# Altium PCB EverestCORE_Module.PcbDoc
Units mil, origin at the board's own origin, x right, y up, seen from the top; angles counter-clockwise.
Board outline not stored, 6 copper layers (Top Layer, Mid-Layer 1, Mid-Layer 2, Mid-Layer 3, Mid-Layer 4, Bottom Layer); 17 components, 0 nets, 306 pads, 67 vias.
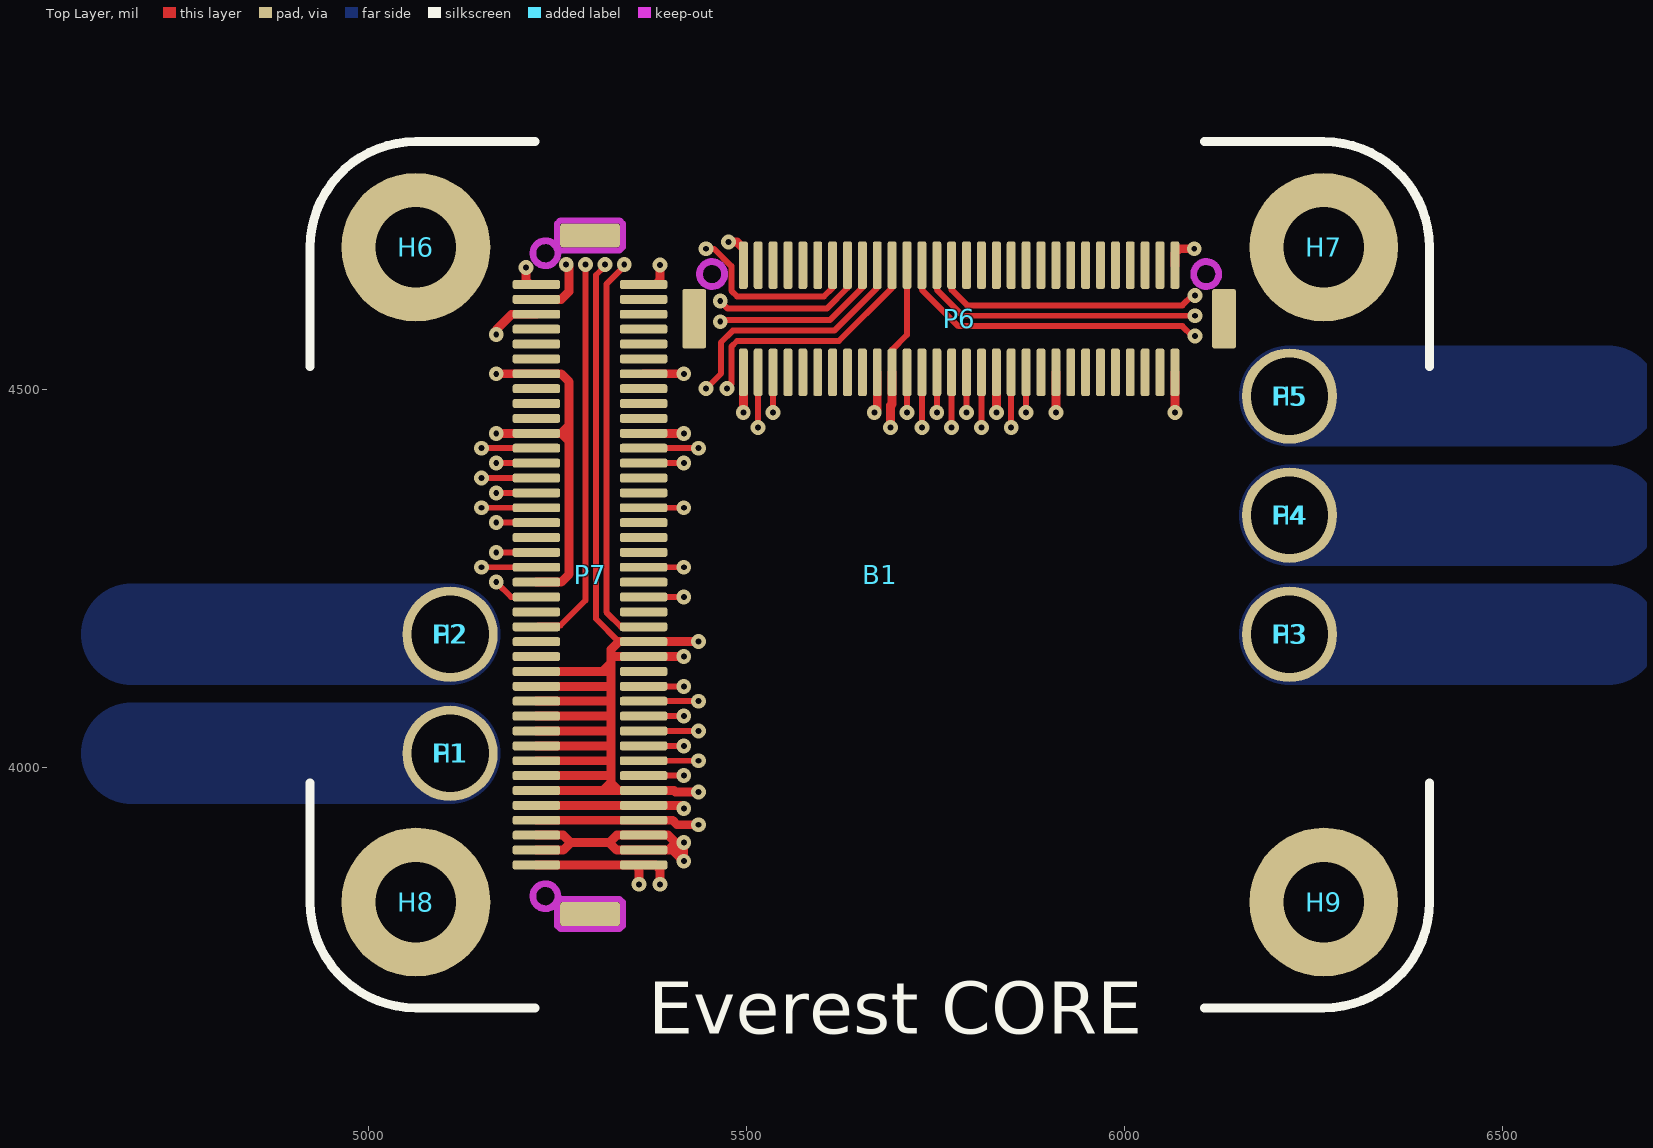
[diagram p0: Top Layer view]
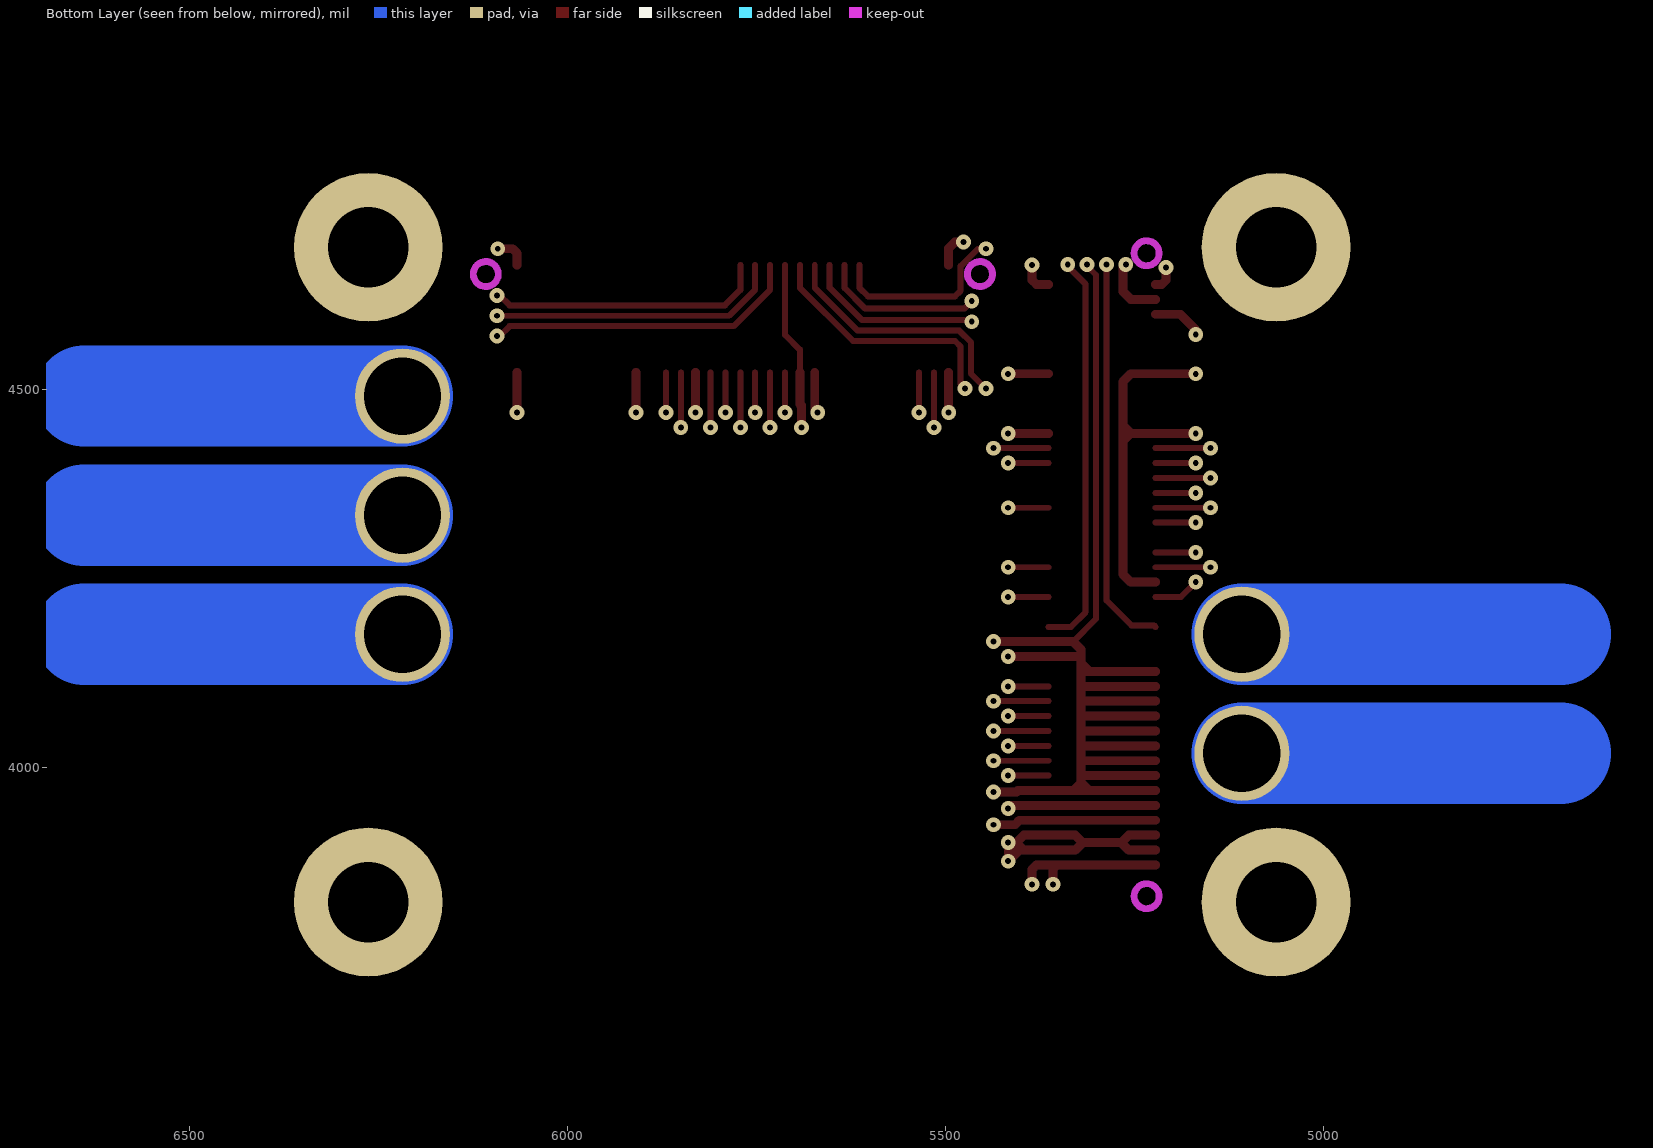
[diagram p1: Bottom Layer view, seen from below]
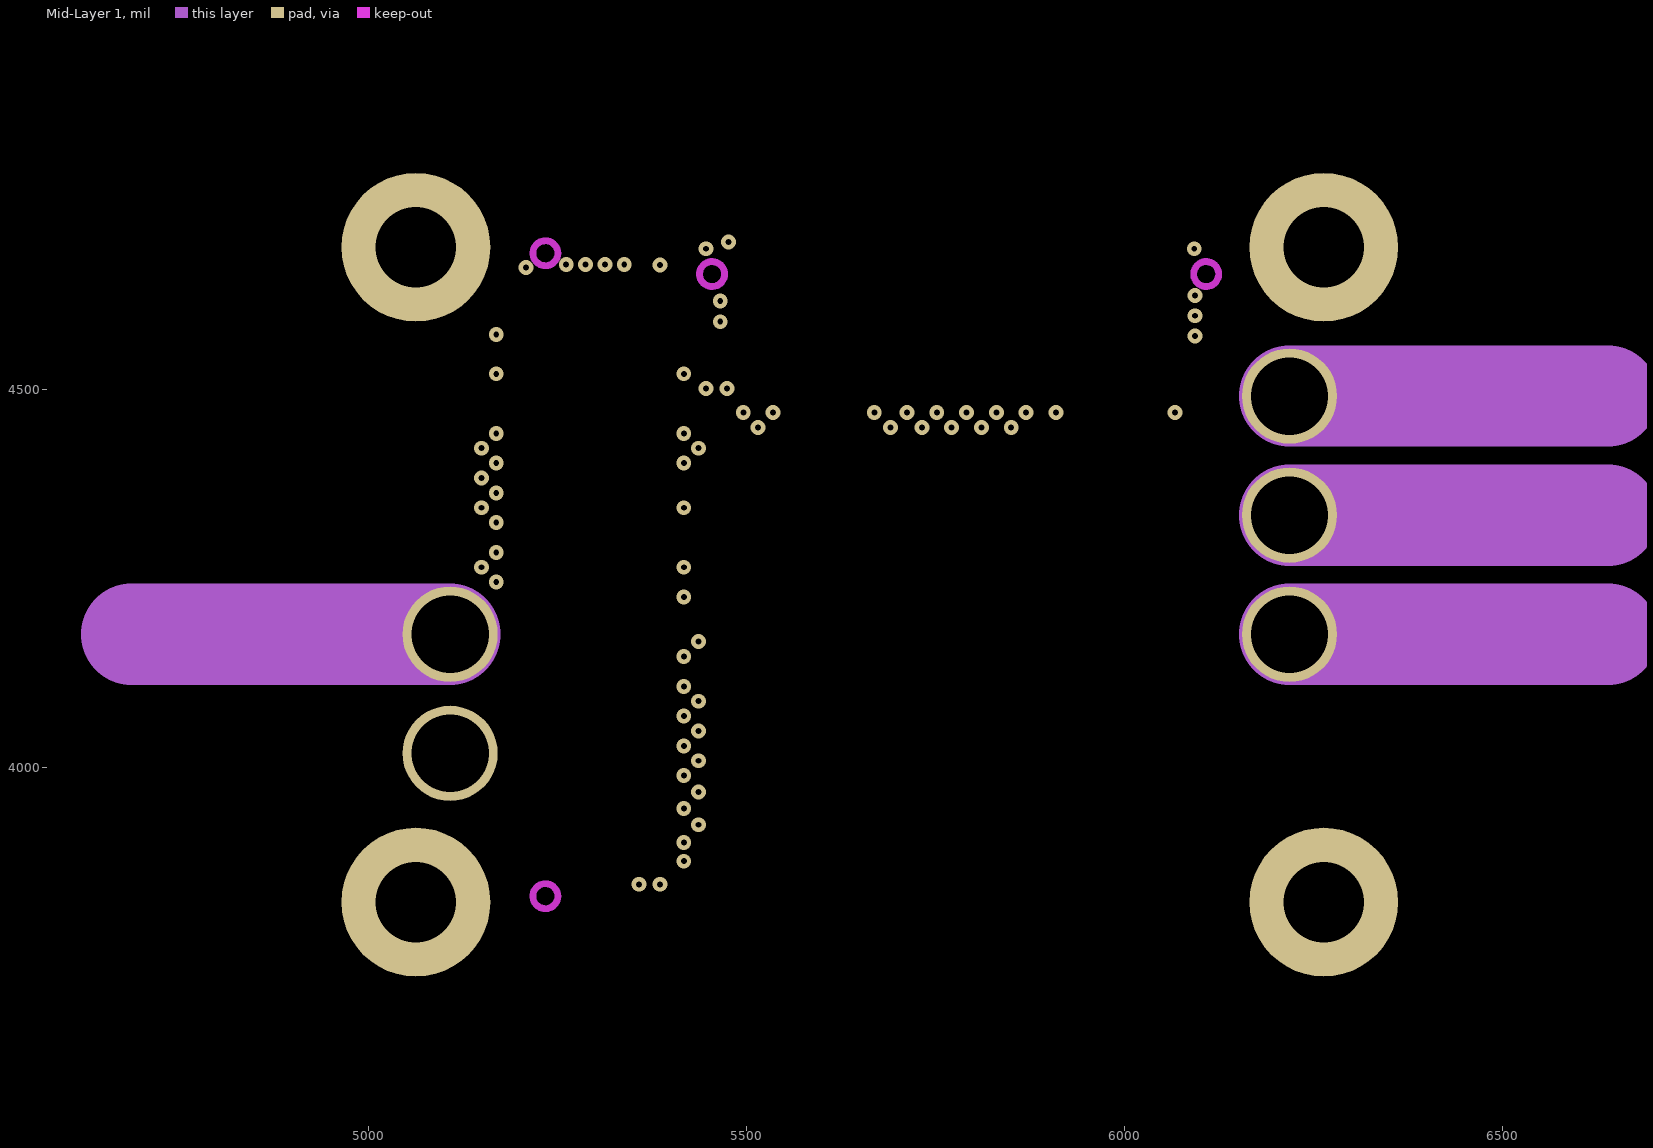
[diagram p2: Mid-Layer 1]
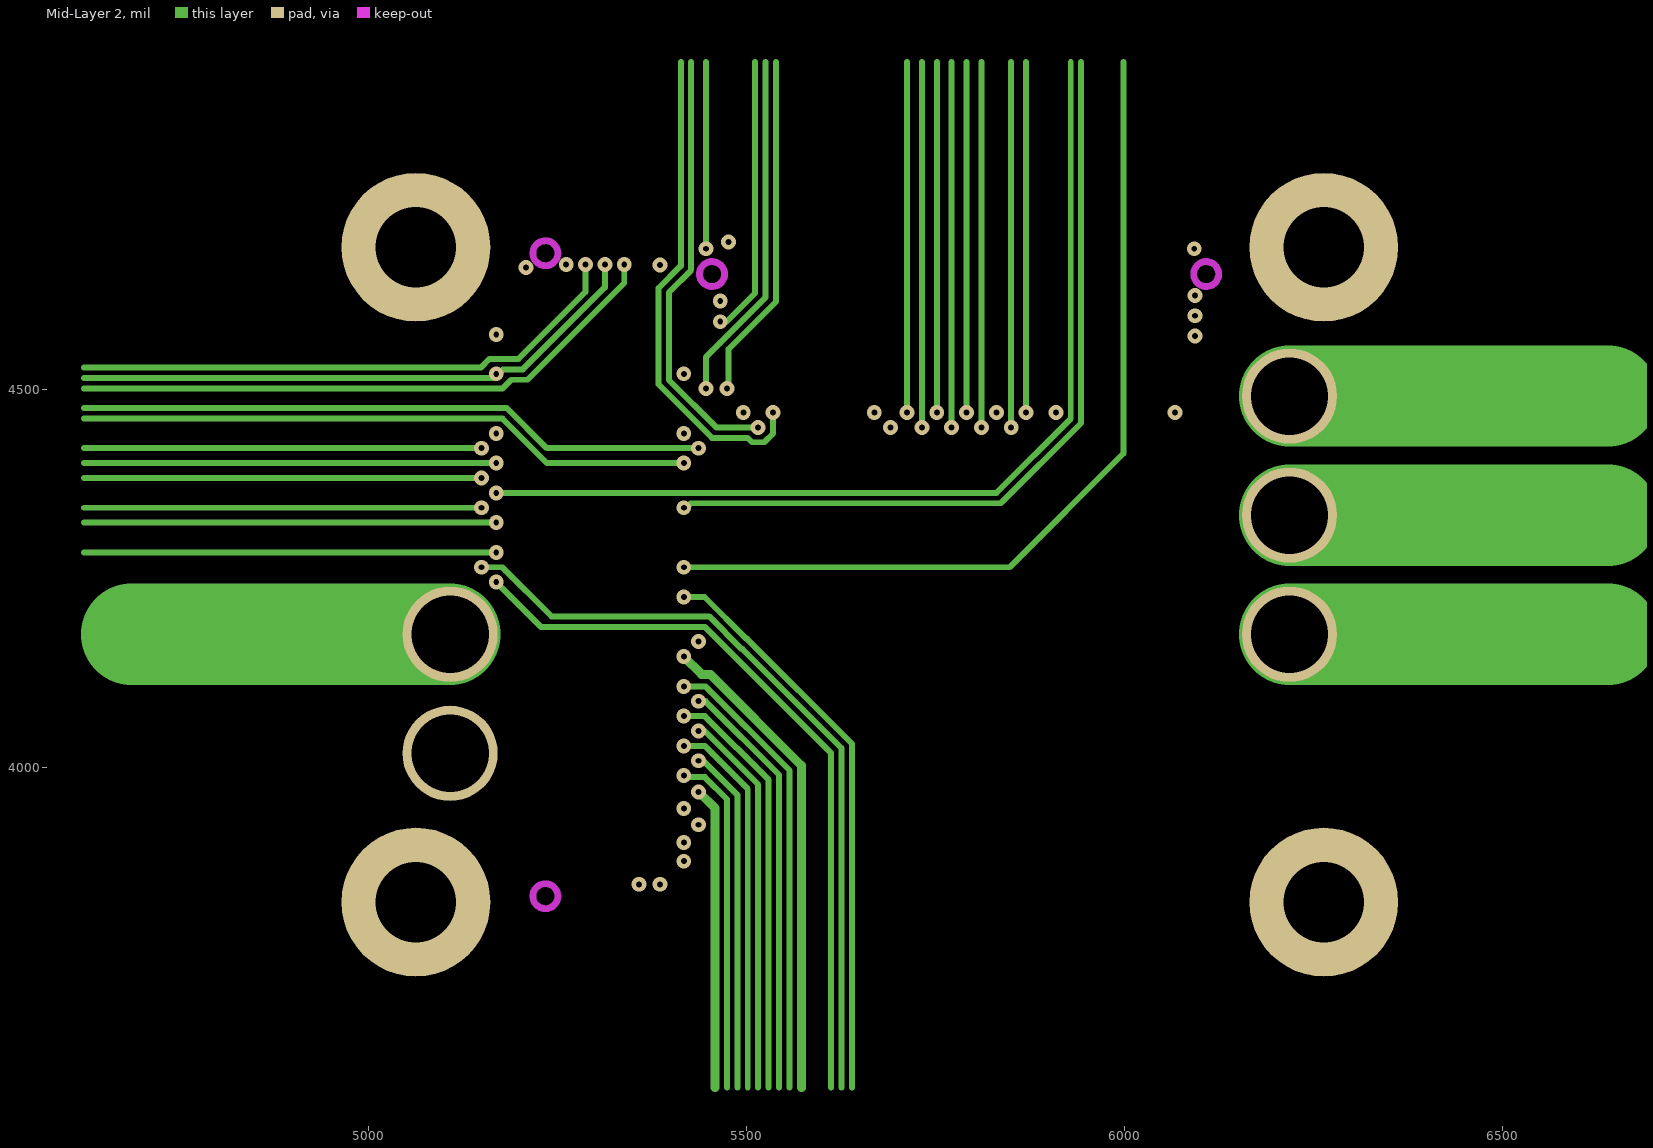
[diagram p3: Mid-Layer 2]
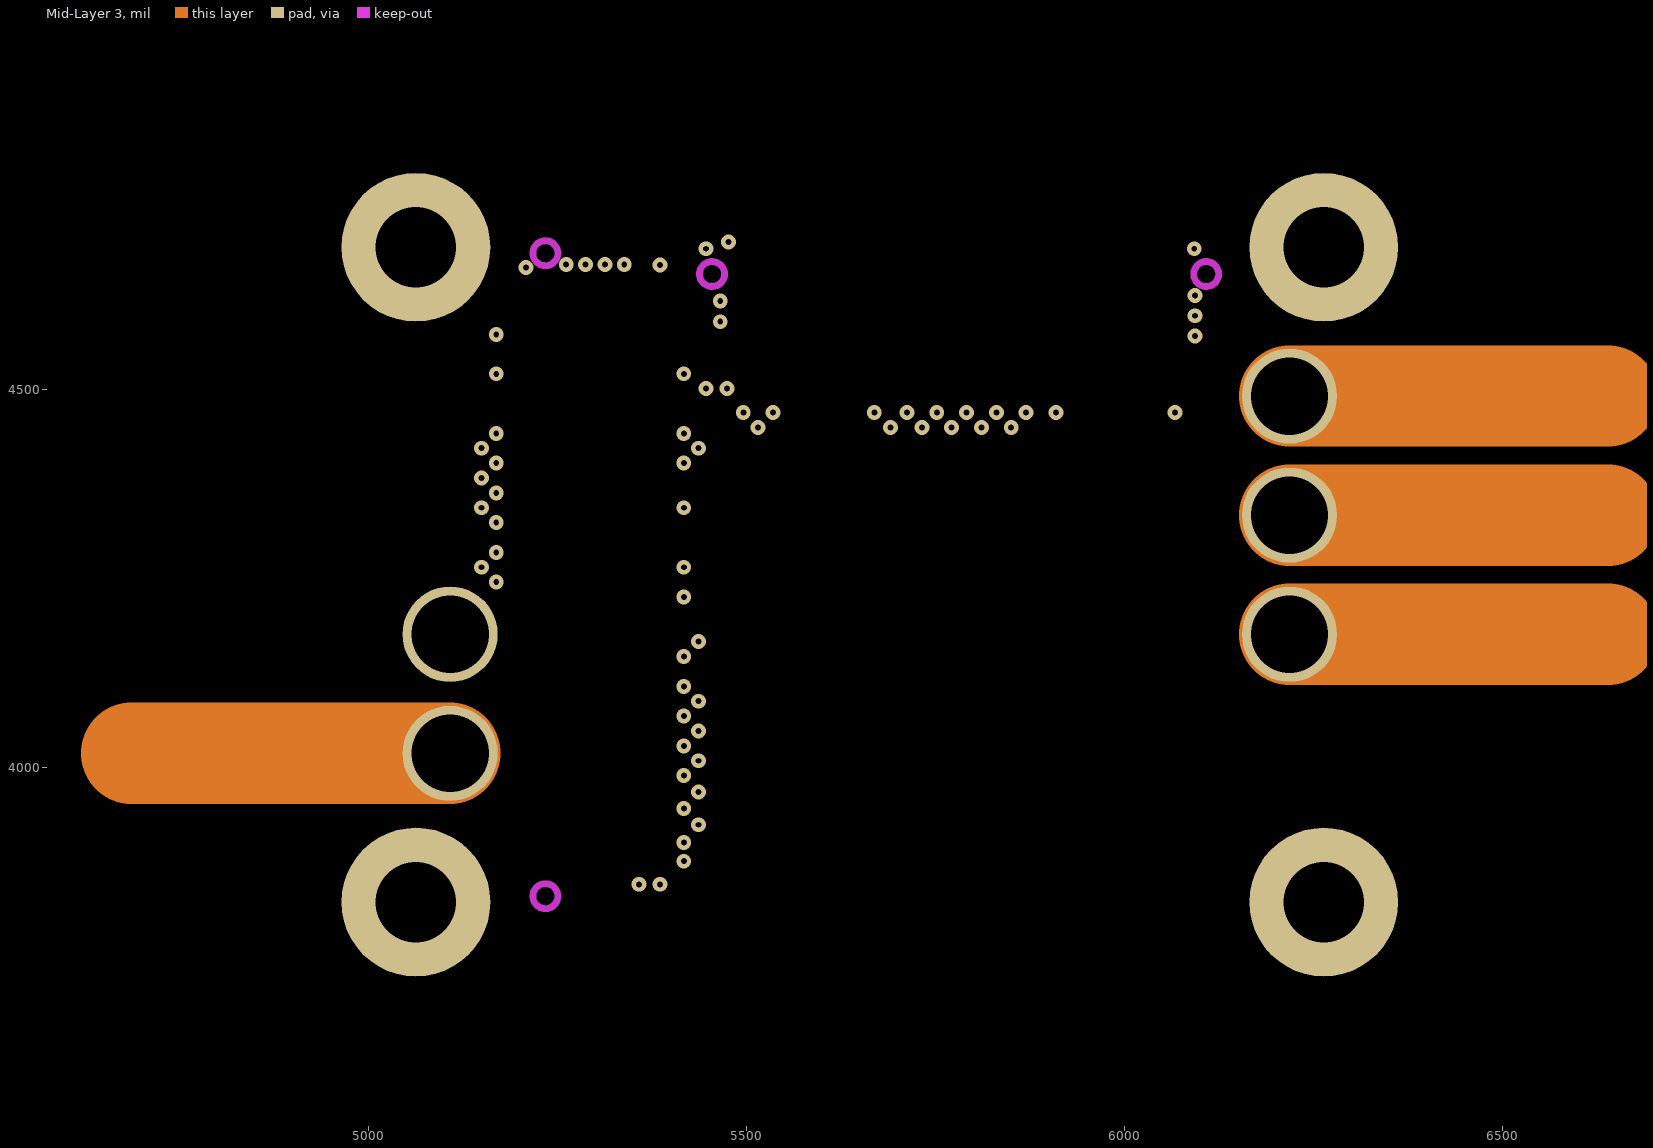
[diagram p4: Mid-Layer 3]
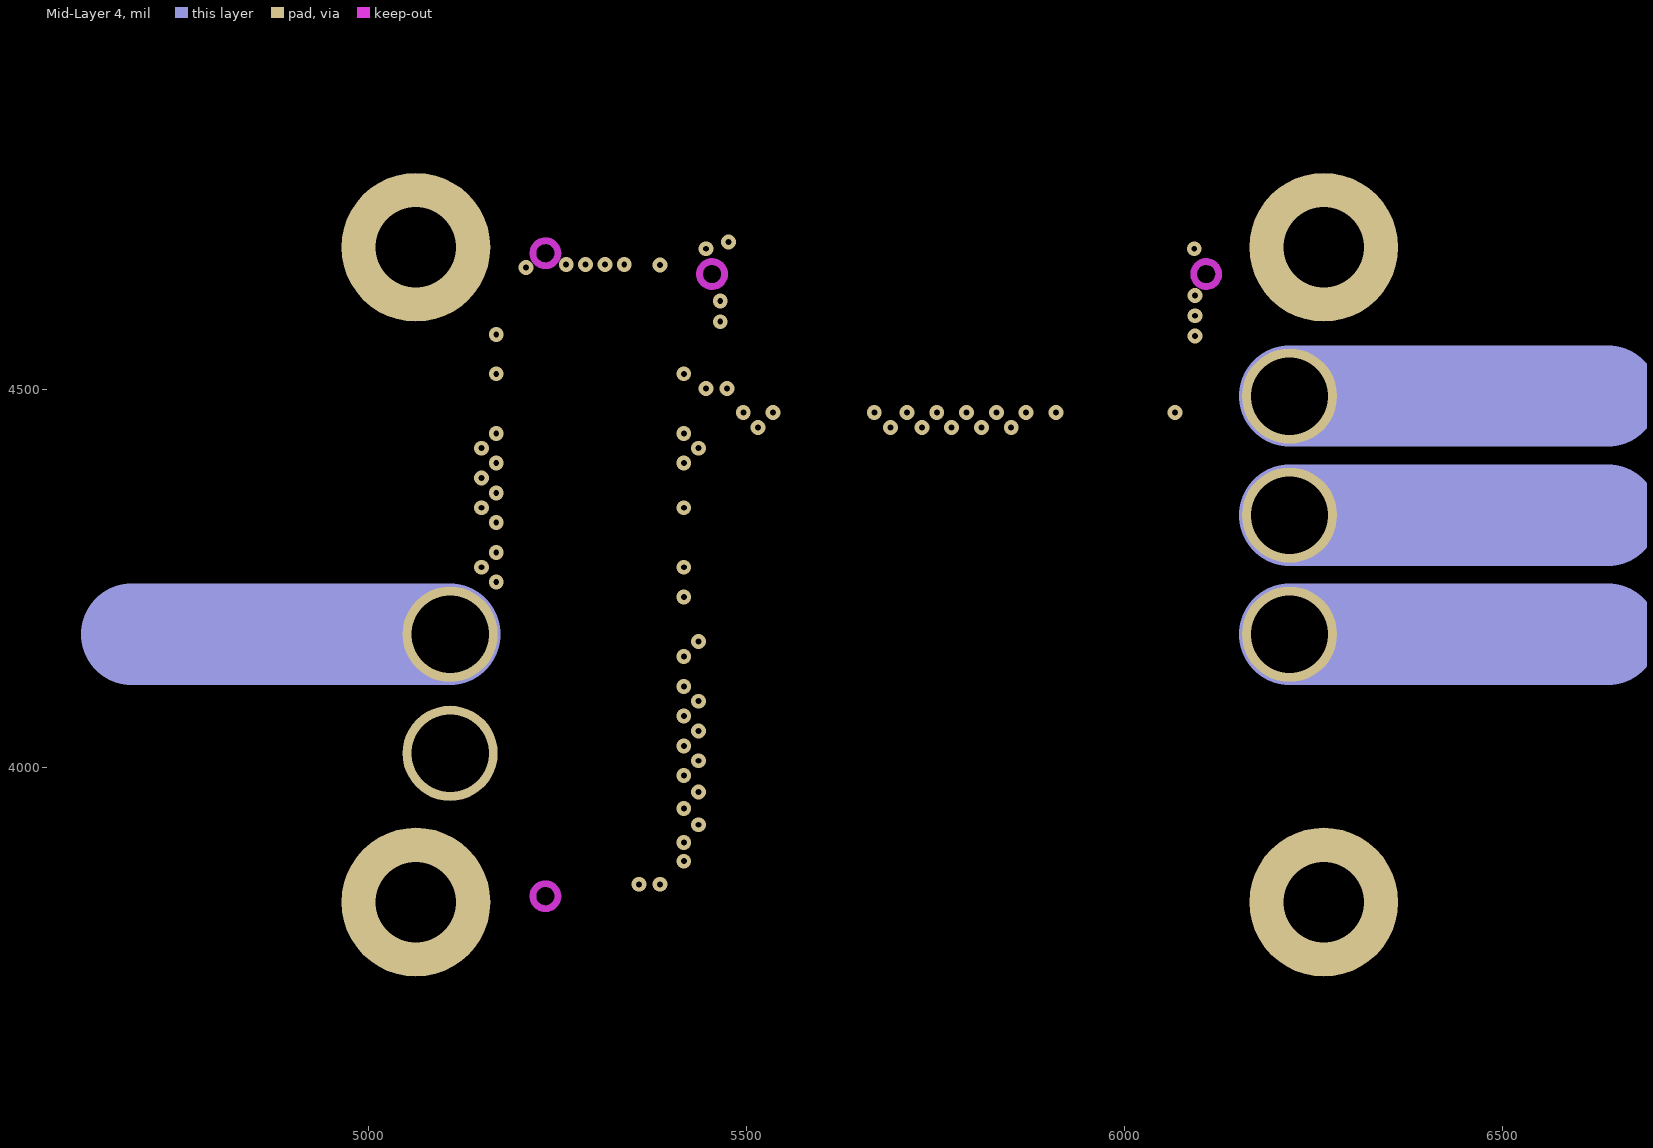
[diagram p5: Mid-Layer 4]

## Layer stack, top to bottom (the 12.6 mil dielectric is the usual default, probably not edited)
Top Solder: solder mask 0.4, Solder Resist, Dk 3.5
Top Layer: signal copper 1.4
Dielectric 1: dielectric 12.6, FR-4, Dk 4.8
Mid-Layer 1: signal copper 1.4
Dielectric4: dielectric 12.6, FR-4, Dk 4.8
Mid-Layer 2: signal copper 1.4
Dielectric5: dielectric 12.6, FR-4, Dk 4.8
Mid-Layer 3: signal copper 1.4
Dielectric3: dielectric 12.6, FR-4, Dk 4.8
Mid-Layer 4: signal copper 1.4
Dielectric2: dielectric 12.6, FR-4, Dk 4.8
Bottom Layer: signal copper 1.4
Bottom Solder: solder mask 0.4, Solder Resist, Dk 3.5

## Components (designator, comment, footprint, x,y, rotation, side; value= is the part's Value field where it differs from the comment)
B1 "Everest_CORE" EVEREST_CORE 5662.6,4255.12 r0 top locked value=-
H1 "Part Number" Hole_1.7mm_Routing 5107.48,4018.9 r0 top locked value=-
H2 "Part Number" Hole_1.7mm_Routing 5107.48,4176.38 r0 top locked value=-
H3 "Part Number" Hole_1.7mm_Routing 6217.72,4176.38 r0 top locked value=-
H4 "Part Number" Hole_1.7mm_Routing 6217.72,4333.86 r0 top locked value=-
H5 "Part Number" Hole_1.7mm_Routing 6217.72,4491.34 r0 top locked value=-
H6 "Part Number" Hole_2.7mm_Routing 5062.2,4688.19 r0 top locked value=-
H7 "Part Number" Hole_2.7mm_Routing 6262.99,4688.19 r0 top locked value=-
H8 "Part Number" Hole_2.7mm_Routing 5062.2,3822.05 r0 top locked value=-
H9 "Part Number" Hole_2.7mm_Routing 6262.99,3822.05 r0 top locked value=-
P1 "Part Number" MillMax_9372-0-15-15-23-27-10-0_HD 5107.48,4018.9 r0 top locked value=-
P2 "Part Number" MillMax_9372-0-15-15-23-27-10-0_HD 5107.48,4176.38 r0 top locked value=-
P3 "Part Number" MillMax_9372-0-15-15-23-27-10-0_HD 6217.72,4176.38 r0 top locked value=-
P4 "Part Number" MillMax_9372-0-15-15-23-27-10-0_HD 6217.72,4333.86 r0 top locked value=-
P5 "Part Number" MillMax_9372-0-15-15-23-27-10-0_HD 6217.72,4491.34 r0 top locked value=-
P6 "HIROSE_DF12(3.0)-60DS-0.5V(86)" HIROSE_DF12(3.0)-60DS-0.5V(86) 5780.71,4593.7 r0 top locked value=-
P7 "HIROSE_DF12(3.0)-80DS-0.5V(86)" HIROSE_DF12(3.0)-80DS-0.5V(86) 5292.52,4255.12 r90 top locked value=-

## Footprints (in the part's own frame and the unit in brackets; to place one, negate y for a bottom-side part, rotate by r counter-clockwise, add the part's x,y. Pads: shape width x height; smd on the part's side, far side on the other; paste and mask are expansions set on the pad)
EVEREST_CORE [mm] "Everest CORE 3D model + Pads + Connectors position"
  rrect20% 2x0.8 on Mech5: 0(-9.4,-11.4) 0(-9.4,11.4)
  rrect20% 0.8x2 on Mech5: 0(-5.9,8.6) 0(11.9,8.6)
  rrect50% 1.6x0.3 on Mech5: 1(-11.2,-9.75) 2(-7.6,-9.75) 3(-11.2,-9.25) 4(-7.6,-9.25) 5(-11.2,-8.75) 6(-7.6,-8.75) 7(-11.2,-8.25) 8(-7.6,-8.25) 9(-11.2,-7.75) 10(-7.6,-7.75) 11(-11.2,-7.25) 12(-7.6,-7.25) 13(-11.2,-6.75) 14(-7.6,-6.75) 15(-11.2,-6.25) 16(-7.6,-6.25) 17(-11.2,-5.75) 18(-7.6,-5.75) 19(-11.2,-5.25) 20(-7.6,-5.25) 21(-11.2,-4.75) 22(-7.6,-4.75) 23(-11.2,-4.25) 24(-7.6,-4.25) 25(-11.2,-3.75) 26(-7.6,-3.75) 27(-11.2,-3.25) 28(-7.6,-3.25) 29(-11.2,-2.75) 30(-7.6,-2.75) 31(-11.2,-2.25) 32(-7.6,-2.25) 33(-11.2,-1.75) 34(-7.6,-1.75) 35(-11.2,-1.25) 36(-7.6,-1.25) 37(-11.2,-0.75) 38(-7.6,-0.75) 39(-11.2,-0.25) 40(-7.6,-0.25) 41(-11.2,0.25) 42(-7.6,0.25) 43(-11.2,0.75) 44(-7.6,0.75) 45(-11.2,1.25) 46(-7.6,1.25) 47(-11.2,1.75) 48(-7.6,1.75) 49(-11.2,2.25) 50(-7.6,2.25) 51(-11.2,2.75) 52(-7.6,2.75) 53(-11.2,3.25) 54(-7.6,3.25) 55(-11.2,3.75) 56(-7.6,3.75) 57(-11.2,4.25) 58(-7.6,4.25) 59(-11.2,4.75) 60(-7.6,4.75) 61(-11.2,5.25) 62(-7.6,5.25) 63(-11.2,5.75) 64(-7.6,5.75) 65(-11.2,6.25) 66(-7.6,6.25) 67(-11.2,6.75) 68(-7.6,6.75) 69(-11.2,7.25) 70(-7.6,7.25) 71(-11.2,7.75) 72(-7.6,7.75) 73(-11.2,8.25) 74(-7.6,8.25) 75(-11.2,8.75) 76(-7.6,8.75) 77(-11.2,9.25) 78(-7.6,9.25) 79(-11.2,9.75) 80(-7.6,9.75)
  rrect50% 0.3x1.6 on Mech5: 1(-4.25,10.4) 2(-4.25,6.8) 3(-3.75,10.4) 4(-3.75,6.8) 5(-3.25,10.4) 6(-3.25,6.8) 7(-2.75,10.4) 8(-2.75,6.8) 9(-2.25,10.4) 10(-2.25,6.8) 11(-1.75,10.4) 12(-1.75,6.8) 13(-1.25,10.4) 14(-1.25,6.8) 15(-0.75,10.4) 16(-0.75,6.8) 17(-0.25,10.4) 18(-0.25,6.8) 19(0.25,10.4) 20(0.25,6.8) 21(0.75,10.4) 22(0.75,6.8) 23(1.25,10.4) 24(1.25,6.8) 25(1.75,10.4) 26(1.75,6.8) 27(2.25,10.4) 28(2.25,6.8) 29(2.75,10.4) 30(2.75,6.8) 31(3.25,10.4) 32(3.25,6.8) 33(3.75,10.4) 34(3.75,6.8) 35(4.25,10.4) 36(4.25,6.8) 37(4.75,10.4) 38(4.75,6.8) 39(5.25,10.4) 40(5.25,6.8) 41(5.75,10.4) 42(5.75,6.8) 43(6.25,10.4) 44(6.25,6.8) 45(6.75,10.4) 46(6.75,6.8) 47(7.25,10.4) 48(7.25,6.8) 49(7.75,10.4) 50(7.75,6.8) 51(8.25,10.4) 52(8.25,6.8) 53(8.75,10.4) 54(8.75,6.8) 55(9.25,10.4) 56(9.25,6.8) 57(9.75,10.4) 58(9.75,6.8) 59(10.25,10.4) 60(10.25,6.8)
  silkscreen extent -18.8,-14.55 18.8,14.55, body extent -17.25,-13 17.25,13, height 10.4
HIROSE_DF12(3.0)-60DS-0.5V(86) [mm] "CONN HEADER 60POS 5MM SMD 0.5MM"
  rrect50% 0.3x1.6 smd: 1(-7.25,1.8) 2(-7.25,-1.8) 3(-6.75,1.8) 4(-6.75,-1.8) 5(-6.25,1.8) 6(-6.25,-1.8) 7(-5.75,1.8) 8(-5.75,-1.8) 9(-5.25,1.8) 10(-5.25,-1.8) 11(-4.75,1.8) 12(-4.75,-1.8) 13(-4.25,1.8) 14(-4.25,-1.8) 15(-3.75,1.8) 16(-3.75,-1.8) 17(-3.25,1.8) 18(-3.25,-1.8) 19(-2.75,1.8) 20(-2.75,-1.8) 21(-2.25,1.8) 22(-2.25,-1.8) 23(-1.75,1.8) 24(-1.75,-1.8) 25(-1.25,1.8) 26(-1.25,-1.8) 27(-0.75,1.8) 28(-0.75,-1.8) 29(-0.25,1.8) 30(-0.25,-1.8) 31(0.25,1.8) 32(0.25,-1.8) 33(0.75,1.8) 34(0.75,-1.8) 35(1.25,1.8) 36(1.25,-1.8) 37(1.75,1.8) 38(1.75,-1.8) 39(2.25,1.8) 40(2.25,-1.8) 41(2.75,1.8) 42(2.75,-1.8) 43(3.25,1.8) 44(3.25,-1.8) 45(3.75,1.8) 46(3.75,-1.8) 47(4.25,1.8) 48(4.25,-1.8) 49(4.75,1.8) 50(4.75,-1.8) 51(5.25,1.8) 52(5.25,-1.8) 53(5.75,1.8) 54(5.75,-1.8) 55(6.25,1.8) 56(6.25,-1.8) 57(6.75,1.8) 58(6.75,-1.8) 59(7.25,1.8) 60(7.25,-1.8)
  round 0 hole 0.6 unplated: H1(-8.3,1.5) H2(8.3,1.5)
  rrect20% 0.8x2 smd: S1(-8.9,0) S2(8.9,0)
  Keep-Out Layer circle w0.23: c8.3,1.5 r0.42
  Keep-Out Layer circle w0.23: c-8.3,1.5 r0.42
  body extent -9.05,-2.3 9.05,2.3, height 2.2
HIROSE_DF12(3.0)-80DS-0.5V(86) [mm] "CONN HEADER 80POS 3MM SMD 0.5MM"
  rrect50% 0.3x1.6 smd paste+0 mask+0.05: 1(-9.75,1.8) 2(-9.75,-1.8) 3(-9.25,1.8) 4(-9.25,-1.8) 5(-8.75,1.8) 6(-8.75,-1.8) 7(-8.25,1.8) 8(-8.25,-1.8) 9(-7.75,1.8) 10(-7.75,-1.8) 11(-7.25,1.8) 12(-7.25,-1.8) 13(-6.75,1.8) 14(-6.75,-1.8) 15(-6.25,1.8) 16(-6.25,-1.8) 17(-5.75,1.8) 18(-5.75,-1.8) 19(-5.25,1.8) 20(-5.25,-1.8) 21(-4.75,1.8) 22(-4.75,-1.8) 23(-4.25,1.8) 24(-4.25,-1.8) 25(-3.75,1.8) 26(-3.75,-1.8) 27(-3.25,1.8) 28(-3.25,-1.8) 29(-2.75,1.8) 30(-2.75,-1.8) 31(-2.25,1.8) 32(-2.25,-1.8) 33(-1.75,1.8) 34(-1.75,-1.8) 35(-1.25,1.8) 36(-1.25,-1.8) 37(-0.75,1.8) 38(-0.75,-1.8) 39(-0.25,1.8) 40(-0.25,-1.8) 41(0.25,1.8) 42(0.25,-1.8) 43(0.75,1.8) 44(0.75,-1.8) 45(1.25,1.8) 46(1.25,-1.8) 47(1.75,1.8) 48(1.75,-1.8) 49(2.25,1.8) 50(2.25,-1.8) 51(2.75,1.8) 52(2.75,-1.8) 53(3.25,1.8) 54(3.25,-1.8) 55(3.75,1.8) 56(3.75,-1.8) 57(4.25,1.8) 58(4.25,-1.8) 59(4.75,1.8) 60(4.75,-1.8) 61(5.25,1.8) 62(5.25,-1.8) 63(5.75,1.8) 64(5.75,-1.8) 65(6.25,1.8) 66(6.25,-1.8) 67(6.75,1.8) 68(6.75,-1.8) 69(7.25,1.8) 70(7.25,-1.8) 71(7.75,1.8) 72(7.75,-1.8) 73(8.25,1.8) 74(8.25,-1.8) 75(8.75,1.8) 76(8.75,-1.8) 77(9.25,1.8) 78(9.25,-1.8) 79(9.75,1.8) 80(9.75,-1.8)
  round 0 hole 0.6 unplated: H1(-10.8,1.5) H2(10.8,1.5)
  rrect20% 0.8x2 smd: S1(-11.4,0) S2(11.4,0)
  Keep-Out Layer circle w0.23: c-10.8,1.5 r0.42
  Keep-Out Layer circle w0.23: c10.8,1.5 r0.42
  body extent -11.55,-2.3 11.55,2.3, height 2.2
Hole_1.7mm_Routing [mm] "Routing hole, plated, 1.7 mm hole diameter"
  round 2.7 hole 1.7 paste+0 mask+0.05: 1(0,0)
  Top Layer pour cut-out: 0,-0.8 -0.306,-0.739 -0.566,-0.566 -0.739,-0.306 -0.8,0 -0.8,0 -0.739,0.306 -0.566,0.566 -0.306,0.739 0,0.8 0,0.8 0.306,0.739 0.566,0.566 0.739,0.306 0.8,0 0.8,0 0.739,-0.306 0.566,-0.566 0.306,-0.739 0,-0.8
  Top Layer pour cut-out: 0,-1.85 -0.708,-1.709 -1.308,-1.308 -1.709,-0.708 -1.85,0 -1.85,0 -1.709,0.708 -1.308,1.308 -0.708,1.709 0,1.85 0,1.85 0.708,1.709 1.308,1.308 1.709,0.708 1.85,0 1.85,0 1.709,-0.708 1.308,-1.308 0.708,-1.709 0,-1.85
  Bottom Layer pour cut-out: 0,-0.8 -0.306,-0.739 -0.566,-0.566 -0.739,-0.306 -0.8,0 -0.8,0 -0.739,0.306 -0.566,0.566 -0.306,0.739 0,0.8 0,0.8 0.306,0.739 0.566,0.566 0.739,0.306 0.8,0 0.8,0 0.739,-0.306 0.566,-0.566 0.306,-0.739 0,-0.8
  Bottom Layer pour cut-out: 0,-1.85 -0.708,-1.709 -1.308,-1.308 -1.709,-0.708 -1.85,0 -1.85,0 -1.709,0.708 -1.308,1.308 -0.708,1.709 0,1.85 0,1.85 0.708,1.709 1.308,1.308 1.709,0.708 1.85,0 1.85,0 1.709,-0.708 1.308,-1.308 0.708,-1.709 0,-1.85
  body extent -0.01,-0.01 0.01,0.01, height 0.01
Hole_2.7mm_Routing [mm] "Routing hole, plated, 2.7mm diameter"
  round 5 hole 2.7: 1(0,0)
  Top Layer pour cut-out: 0,3.511 1.339,3.244 2.475,2.486 3.234,1.35 3.5,0.011 3.5,0.011 3.5,-0.011 3.234,-1.35 2.475,-2.486 1.339,-3.244 0,-3.511 0,-3.511 -1.344,-3.244 -2.483,-2.483 -3.244,-1.344 -3.511,0 -3.511,0 -3.244,1.344 -2.483,2.483 -1.344,3.244 0,3.511
  Bottom Layer pour cut-out: 0,3.511 1.339,3.244 2.475,2.486 3.234,1.35 3.5,0.011 3.5,0.011 3.5,-0.011 3.234,-1.35 2.475,-2.486 1.339,-3.244 0,-3.511 0,-3.511 -1.344,-3.244 -2.483,-2.483 -3.244,-1.344 -3.511,0 -3.511,0 -3.244,1.344 -2.483,2.483 -1.344,3.244 0,3.511
  Multi-Layer pour cut-out: 0,3.5 1.339,3.234 2.475,2.475 3.234,1.339 3.5,0 3.5,0 3.234,-1.339 2.475,-2.475 1.339,-3.234 0,-3.5 0,-3.5 -1.339,-3.234 -2.475,-2.475 -3.234,-1.339 -3.5,0 -3.5,0 -3.234,1.339 -2.475,2.475 -1.339,3.234 0,3.5
  body extent -0.01,-0.01 0.01,0.01, height 0.01
MillMax_9372-0-15-15-23-27-10-0_HD [mm] "MillMax receptacle for MillMax 6142, gold plated, pass-through"
  round 3.2 hole 2.6: 1(0,0)
  body extent -1.5,-1.5 1.5,1.5, height 0.32

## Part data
B1: library part EVEREST_CORE, "Everest CORE high-performance Servo Drive from Ingenia Motion Control.", ManufacturerName=Ingenia, ManufacturerPN=EVE-CORE, Package Type=-, TemperatureMaxC=85, TemperatureMinC=-40
H1 H2 H3 H4 H5: library part Hole_1.7mm_Routing, "Mounting, plated hole, 1.7 mm diameter", ManufacturerName=Ingenia, ManufacturerPN=-, Package Type=NO, TemperatureMaxC=0
H6 H7 H8 H9: library part Hole_2.7mm_Routing, "Mounting, plated hole, 2.7 mm diameter", ManufacturerName=Ingenia, ManufacturerPN=-, Package Type=NO
P1 P2 P3 P4 P5: library part "Header 1", "1pin, receptacle for MillMax 6142, pass-through", ManufacturerName=MillMax, ManufacturerPN=9372-0-15-15-23-27-10-0, Package Name=MillMax_9372-0-15-15-23-27-10-0, Package Type=TH, Supplier Part Number 1=ED1048-ND, TemperatureMaxC=125, TemperatureMinC=-55
P6: library part Header_30X2_MALE, "Connector SMD Mezzanine, 60 ways, 0.5mm pitch, 3mm stack height. Male", ManufacturerName=Hirose, ManufacturerPN=DF12(3.0)-60DS-0.5V(86), Package Name="SMD connector 60 ways", Package Type=SM, Supplier Part Number 1=H5207CT-ND, TemperatureMaxC=125, TemperatureMinC=-45
P7: library part Header_40x2_MALE, "Connector SMD Mezzanine, 80 ways, 0.5mm pitch, 3mm stack height. Male with metal fitting and boss", ManufacturerName=Hirose, ManufacturerPN=DF12(3.0)-80DS-0.5V(86), Package Name="SMD connector 80 ways male", Package Type=SM, Supplier Part Number 1=H5208CT-ND, TemperatureMaxC=125, TemperatureMinC=-45

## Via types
v1: diameter 19.68, hole 7.87, Top Layer to Bottom Layer, 67 vias

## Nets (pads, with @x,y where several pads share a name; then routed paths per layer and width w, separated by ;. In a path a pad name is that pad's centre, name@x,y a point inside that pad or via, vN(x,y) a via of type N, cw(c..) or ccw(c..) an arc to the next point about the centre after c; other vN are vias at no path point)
pads on no net: B1.0 B1.1 B1.2 B1.3 B1.4 B1.5 B1.6 B1.7 B1.8 B1.9 B1.10 B1.11 B1.12 B1.13 B1.14 B1.15 B1.16 B1.17 B1.18 B1.19 B1.20 B1.21 B1.22 B1.23 B1.24 B1.25 B1.26 B1.27 B1.28 B1.29 B1.30 B1.31 B1.32 B1.33 B1.34 B1.35 B1.36 B1.37 B1.38 B1.39 B1.40 B1.41 B1.42 B1.43 B1.44 B1.45 B1.46 B1.47 B1.48 B1.49 B1.50 B1.51 B1.52 B1.53 B1.54 B1.55 B1.56 B1.57 B1.58 B1.59 B1.60 B1.61 B1.62 B1.63 B1.64 B1.65 B1.66 B1.67 B1.68 B1.69 B1.70 B1.71 B1.72 B1.73 B1.74 B1.75 B1.76 B1.77 B1.78 B1.79 B1.80 H1.1 H2.1 H3.1 H4.1 H5.1 H6.1 H7.1 H8.1 H9.1 P1.1 P2.1 P3.1 P4.1 P5.1 P6.1 P6.2 P6.3 P6.4 P6.5 P6.6 P6.7 P6.8 P6.9 P6.10 P6.11 P6.12 P6.13 P6.14 P6.15 P6.16 P6.17 P6.18 P6.19 P6.20 P6.21 P6.22 P6.23 P6.24 P6.25 P6.26 P6.27 P6.28 P6.29 P6.30 P6.31 P6.32 P6.33 P6.34 P6.35 P6.36 P6.37 P6.38 P6.39 P6.40 P6.41 P6.42 P6.43 P6.44 P6.45 P6.46 P6.47 P6.48 P6.49 P6.50 P6.51 P6.52 P6.53 P6.54 P6.55 P6.56 P6.57 P6.58 P6.59 P6.60 P6.H1 P6.H2 P6.S1 P6.S2 P7.1 P7.2 P7.3 P7.4 P7.5 P7.6 P7.7 P7.8 P7.9 P7.10 P7.11 P7.12 P7.13 P7.14 P7.15 P7.16 P7.17 P7.18 P7.19 P7.20 P7.21 P7.22 P7.23 P7.24 P7.25 P7.26 P7.27 P7.28 P7.29 P7.30 P7.31 P7.32 P7.33 P7.34 P7.35 P7.36 P7.37 P7.38 P7.39 P7.40 P7.41 P7.42 P7.43 P7.44 P7.45 P7.46 P7.47 P7.48 P7.49 P7.50 P7.51 P7.52 P7.53 P7.54 P7.55 P7.56 P7.57 P7.58 P7.59 P7.60 P7.61 P7.62 P7.63 P7.64 P7.65 P7.66 P7.67 P7.68 P7.69 P7.70 P7.71 P7.72 P7.73 P7.74 P7.75 P7.76 P7.77 P7.78 P7.79 P7.80 P7.H1 P7.H2 P7.S1 P7.S2
copper on no net: | length 43453.8
  Top Layer w7.87: v1(5148.82,4264.96) 5221.65,4264.96 ; v1(5148.82,4343.7) 5221.65,4343.7 ; v1(5148.82,4383.07) 5221.65,4383.07 ; v1(5148.82,4422.44) 5221.65,4422.44 ; v1(5168.5,4245.28) 5188.19,4225.59 5221.65,4225.59 ; v1(5168.5,4284.65) 5221.65,4284.65 ; v1(5168.5,4324.02) 5221.65,4324.02 ; v1(5168.5,4363.39) 5221.65,4363.39 ; v1(5168.5,4402.76) 5221.65,4402.76 ; 5221.65,4186.22 5223.62,4188.19 5253.53,4188.19 5286.61,4221.28 v1(5286.61,4665.55) ; v1(5312.2,4665.55) 5312.2,4663.3 5300.39,4651.49 5300.39,4196.84 5330.7,4166.54 ; v1(5337.8,4665.55) 5337.8,4662.98 5314.17,4639.36 5314.17,4205.53 5333.48,4186.22 5363.39,4186.22 ; 5363.39,3989.37 v1(5416.54,3989.37) ; 5363.39,4009.06 v1(5436.22,4009.06) ; 5363.39,4028.74 v1(5416.54,4028.74) ; 5363.39,4048.43 v1(5436.22,4048.43) ; 5363.39,4068.11 v1(5416.54,4068.11) ; 5363.39,4087.8 v1(5436.22,4087.8) ; 5363.39,4107.48 v1(5416.54,4107.48) ; 5363.39,4225.59 v1(5416.54,4225.59) ; 5363.39,4264.96 v1(5416.54,4264.96) ; 5363.39,4343.7 v1(5416.54,4343.7) ; 5363.39,4402.76 v1(5416.54,4402.76) ; 5363.39,4422.44 v1(5436.22,4422.44) ; v1(5446.06,4501.18) 5446.06,4501.46 5465.75,4521.15 5465.75,4562.39 5481.32,4577.95 5615.73,4577.95 5672.44,4634.66 5672.44,4664.57 ; v1(5446.06,4686.22) 5456.58,4686.22 5479.53,4663.27 5479.53,4630.72 5487.02,4623.23 5601.95,4623.23 5613.39,4634.66 5613.39,4664.57 ; v1(5464.76,4589.76) 5466.73,4591.73 5609.83,4591.73 5652.76,4634.66 5652.76,4664.57 ; v1(5464.76,4616.9) 5474.18,4607.48 5606.09,4607.48 5633.07,4634.46 5633.07,4664.57 ; v1(5473.62,4501.18) 5479.53,4507.09 5479.53,4556.68 5487.02,4564.17 5621.64,4564.17 5692.13,4634.66 5692.13,4664.57 ; v1(5514.96,4450) 5514.96,4522.83 ; v1(5534.65,4469.69) 5534.65,4522.83 ; 5692.13,4522.83 5692.13,4552.74 5711.81,4572.43 5711.81,4664.57 ; v1(5711.81,4469.69) 5711.81,4522.83 ; v1(5731.5,4450) 5731.5,4522.83 ; 5731.5,4664.57 5731.5,4632.09 5779.72,4583.86 6075.87,4583.86 6088.67,4571.06 v1(6092.72,4571.06) ; v1(5751.18,4469.69) 5751.18,4522.83 ; 5751.18,4664.57 5751.18,4632.07 5785.62,4597.64 v1(6092.72,4597.64) ; v1(5770.87,4450) 5770.87,4522.83 ; 5770.87,4664.57 5770.87,4631.88 5791.33,4611.42 6075.87,4611.42 6088.67,4624.21 v1(6092.72,4624.21) ; v1(5790.55,4469.69) 5790.55,4522.83 ; v1(5810.24,4450) 5810.24,4522.83 ; v1(5849.61,4450) 5849.61,4522.83 ; v1(5869.29,4469.69) 5869.29,4522.83
  Top Layer w11.81: v1(5168.5,4442.13) 5221.65,4442.13 5254.34,4442.13 ; v1(5168.5,4520.87) 5221.65,4520.87 5254.34,4520.87 5264.96,4510.25 5264.96,4452.74 ; v1(5168.5,4573.03) 5168.5,4579.15 5188.96,4599.61 5221.65,4599.61 ; v1(5207.87,4661.61) 5207.87,4644.88 5213.78,4638.98 5221.65,4638.98 ; 5221.65,3871.26 5363.39,3871.26 5379.13,3871.26 5385.04,3865.35 v1(5385.04,3845.67) ; 5221.65,3890.95 5257.09,3890.95 5266.93,3900.79 ; 5221.65,3910.63 5257.09,3910.63 5266.93,3900.79 ; 5221.65,3930.32 5363.39,3930.32 5401.66,3930.32 5407.57,3924.41 v1(5436.22,3924.41) ; 5221.65,3950 5363.39,3950 5412.6,3950 v1(5416.54,3946.06) ; 5221.65,3969.69 5330.7,3969.69 ; 5221.65,3989.37 5319.99,3989.37 ; 5221.65,4009.06 5319.99,4009.06 ; 5221.65,4028.74 5319.99,4028.74 ; 5221.65,4048.43 5319.99,4048.43 ; 5221.65,4068.11 5319.99,4068.11 ; 5221.65,4087.8 5319.99,4087.8 ; 5221.65,4107.48 5319.99,4107.48 ; 5221.65,4127.17 5309.25,4127.17 ; 5221.65,4245.28 5254.34,4245.28 5264.96,4255.89 5264.96,4431.51 ; 5221.65,4619.29 5254.34,4619.29 5264.96,4629.91 5264.96,4661.61 v1(5261.02,4665.55) ; 5309.46,3969.69 5320.08,3980.3 ; 5319.87,4137.78 5309.25,4127.17 ; 5319.99,4127.17 5309.25,4127.17 ; 5320.08,4146.85 v1(5416.54,4146.85) ; 5351.57,3871.26 5357.48,3865.35 v1(5357.48,3845.67) ; 5363.39,4442.13 v1(5416.54,4442.13) ; 5363.39,4520.87 v1(5416.54,4520.87) ; 5363.39,4638.98 5379.13,4638.98 5385.04,4644.88 v1(5385.04,4664.57) ; v1(5436.22,3967.72) 5405.71,3967.72 5403.74,3969.69 5363.39,3969.69 5330.7,3969.69 ; v1(5436.22,4166.54) 5363.39,4166.54 5330.7,4166.54 5320.08,4155.92 5320.08,3980.3 ; v1(5475.59,4695.08) 5486.97,4695.08 5495.28,4686.78 5495.28,4664.57 ; v1(5495.28,4469.69) 5495.28,4522.83 ; v1(5668.5,4469.69) 5672.44,4473.62 5672.44,4522.83 ; v1(5690.16,4450) 5690.16,4478.65 5692.13,4480.62 5692.13,4522.83 ; v1(5829.92,4469.69) 5829.92,4522.83 ; v1(5908.66,4469.69) 5908.66,4522.83 ; v1(6066.14,4469.69) 6066.14,4522.83 ; 6066.14,4664.57 6066.14,4680.31 6072.05,4686.22 v1(6091.73,4686.22) ; 5254.34,4442.13 5264.96,4431.51 ; 5254.34,4442.13 5264.96,4452.74 ; 5264.96,4431.51 5264.96,4452.74 ; 5266.93,3900.79 5318.11,3900.79 ; 5318.11,3900.79 5327.95,3890.95 5363.39,3890.95 5395.87,3890.95 ; 5318.11,3900.79 5327.95,3910.63 5363.39,3910.63 5395.87,3910.63 5405.71,3900.79 ; 5320.08,3980.3 5330.7,3969.69 ; 5395.87,3890.95 5405.71,3900.79 ; 5395.87,3890.95 5401.77,3890.95 v1(5416.54,3876.18) ; 5405.71,3900.79 v1(5416.54,3900.79) v1(5416.54,3876.18) ; 5405.71,3900.79 5405.71,3887.04 v1(5416.54,3876.18)
  Mid-Layer 1 w133.86: 4686.22,4176.38 5107.48,4176.38 ; 6217.72,4176.38 6638.98,4176.38 ; 6217.72,4333.86 6638.98,4333.86 ; 6217.72,4491.34 6638.98,4491.34
  Mid-Layer 2 w7.87: 4623.23,4284.65 v1(5168.5,4284.65) ; 4623.23,4324.02 v1(5168.5,4324.02) ; 4623.23,4343.7 v1(5148.82,4343.7) ; 4623.23,4383.07 v1(5148.82,4383.07) ; 4623.23,4402.76 v1(5168.5,4402.76) ; 4623.23,4422.44 v1(5148.82,4422.44) ; 4623.23,4461.81 5176.66,4461.81 5235.71,4402.76 v1(5416.54,4402.76) ; 4623.23,4475.59 5182.37,4475.59 5235.51,4422.44 v1(5436.22,4422.44) ; 4623.23,4501.18 5176.66,4501.18 5188.47,4512.99 5209.84,4512.99 5337.8,4640.95 v1(5337.8,4665.55) ; 4623.23,4515.58 5163.22,4515.58 v1(5168.5,4520.87) 5171.7,4520.87 5177.61,4526.77 5203.74,4526.77 5312.2,4635.24 v1(5312.2,4665.55) ; 4623.23,4529.36 5148.45,4529.36 5159.65,4540.55 5198.03,4540.55 5286.61,4629.13 v1(5286.61,4665.55) ; v1(5148.82,4264.96) 5176.66,4264.96 5241.62,4200 5450.08,4200 5493.39,4156.69 5494.29,4156.69 5625.2,4025.79 5625.2,3576.97 ; v1(5168.5,4245.28) 5227.56,4186.22 5444.37,4186.22 5611.42,4019.18 5611.42,3576.97 ; v1(5168.5,4363.39) 5830.2,4363.39 5928.35,4461.53 5928.35,4933.27 ; 5412.6,4933.27 5412.6,4663.58 5383.07,4634.06 5383.07,4507.01 5453.86,4436.22 5500.9,4436.22 5506.81,4430.32 5523.11,4430.32 5534.65,4441.85 v1(5534.65,4469.69) ; v1(5416.54,3989.37) 5418.5,3987.4 5444.37,3987.4 5473.62,3958.15 5473.62,3576.97 ; v1(5416.54,4028.74) 5444.37,4028.74 5501.18,3971.93 5501.18,3576.97 ; v1(5416.54,4068.11) 5444.37,4068.11 5528.74,3983.74 5528.74,3576.97 ; v1(5416.54,4107.48) 5445.08,4107.48 5556.3,3996.26 5556.3,3576.97 ; v1(5416.54,4225.59) 5443.98,4225.59 5499.1,4170.47 5500,4170.47 5638.98,4031.49 5638.98,3576.97 ; v1(5416.54,4264.96) 5847.64,4264.96 5998.23,4415.55 5998.23,4933.27 ; v1(5416.54,4343.7) 5419.73,4343.7 5425.64,4349.61 5835.91,4349.61 5942.13,4455.82 5942.13,4933.27 ; 5426.38,4933.27 5426.38,4657.88 5396.85,4628.35 5396.85,4512.71 5459.56,4450 v1(5514.96,4450) ; v1(5436.22,4009.06) 5442.21,4009.06 5487.4,3963.86 5487.4,3576.97 ; v1(5436.22,4048.43) 5444.18,4048.43 5514.96,3977.64 5514.96,3576.97 ; v1(5436.22,4087.8) 5445.08,4087.8 5542.52,3990.35 5542.52,3576.97 ; v1(5446.06,4501.18) 5446.06,4543.22 5524.8,4621.96 5524.8,4933.27 ; v1(5446.06,4686.22) 5446.06,4933.27 ; v1(5464.76,4589.76) 5473.12,4589.76 5511.02,4627.67 5511.02,4933.27 ; v1(5473.62,4501.18) 5475.7,4503.26 5475.7,4553.38 5538.58,4616.26 5538.58,4933.27 ; v1(5711.81,4469.69) 5711.81,4933.27 ; v1(5731.5,4450) 5731.5,4933.27 ; v1(5751.18,4469.69) 5751.18,4933.27 ; v1(5770.87,4450) 5770.87,4933.27 ; v1(5790.55,4469.69) 5790.55,4933.27 ; v1(5810.24,4450) 5810.24,4933.27 ; v1(5849.61,4450) 5849.61,4933.27 ; v1(5869.29,4469.69) 5869.29,4933.27
  Mid-Layer 2 w11.81: v1(5416.54,4146.85) 5440.16,4123.23 5451.6,4123.23 5572.05,4002.78 5572.05,3576.97 ; v1(5436.22,3967.72) 5457.87,3946.06 5457.87,3576.97
  Mid-Layer 2 w133.86: 4686.22,4176.38 5107.48,4176.38 ; 6217.72,4176.38 6638.98,4176.38 ; 6217.72,4333.86 6638.98,4333.86 ; 6217.72,4491.34 6638.98,4491.34
  Mid-Layer 3 w133.86: 4686.22,4018.9 5107.48,4018.9 ; 6217.72,4176.38 6638.98,4176.38 ; 6217.72,4333.86 6638.98,4333.86 ; 6217.72,4491.34 6638.98,4491.34
  Mid-Layer 4 w133.86: 4686.22,4176.38 5107.48,4176.38 ; 6217.72,4176.38 6638.98,4176.38 ; 6217.72,4333.86 6638.98,4333.86 ; 6217.72,4491.34 6638.98,4491.34
  Bottom Layer w133.86: 4686.22,4018.9 5107.48,4018.9 ; 4686.22,4176.38 5107.48,4176.38 ; 6217.72,4176.38 6638.98,4176.38 ; 6217.72,4333.86 6638.98,4333.86 ; 6217.72,4491.34 6638.98,4491.34

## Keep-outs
Top Layer:
  lines w7.87: 5249.15,3790.61 5249.15,3821.99 5253.27,3826.11 5331.77,3826.11 5335.89,3821.99 5335.89,3790.61 5331.77,3786.49 5253.27,3786.49 5249.15,3790.61 ; 5249.15,4688.25 5253.27,4684.13 5331.77,4684.13 5335.89,4688.25 5335.89,4719.62 5331.77,4723.75 5253.27,4723.75 5249.15,4719.62 5249.15,4688.25

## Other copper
Top Layer:
  pour cut-out: 4963.78,3802.36 ccw(c5042.52,3802.36) 5042.52,3723.62 5704.92,3723.62 5704.92,3802.36 5234.92,3802.36 cw(c5234.92,3861.42) 5177.38,3848.13 ccw(c5062.19,3822.06) 5085.09,3937.92 cw(c5095.65,3996) 5036.61,3995.98 5036.61,4514.25 cw(c5095.67,4514.25) 5085.08,4572.35 ccw(c5062.23,4688.21) 5177.4,4662.09 cw(c5234.94,4648.82) 5234.92,4707.87 6090.28,4707.87 cw(c6090.28,4648.82) 6147.82,4662.1 ccw(c6263.01,4688.18) 6240.11,4572.32 cw(c6229.54,4514.23) 6288.58,4514.25 6288.58,3995.98 cw(c6229.53,3995.98) 6240.11,3937.89 ccw(c6262.97,3822.03) 6147.8,3848.14 cw(c6090.26,3861.41) 6090.28,3802.36 5704.92,3802.36 5704.92,3723.62 6282.68,3723.62 ccw(c6282.68,3802.36) 6361.42,3802.36 6361.42,4707.87 ccw(c6282.68,4707.87) 6282.68,4786.61 5042.52,4786.61 ccw(c5042.52,4707.87) 4963.78,4707.87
